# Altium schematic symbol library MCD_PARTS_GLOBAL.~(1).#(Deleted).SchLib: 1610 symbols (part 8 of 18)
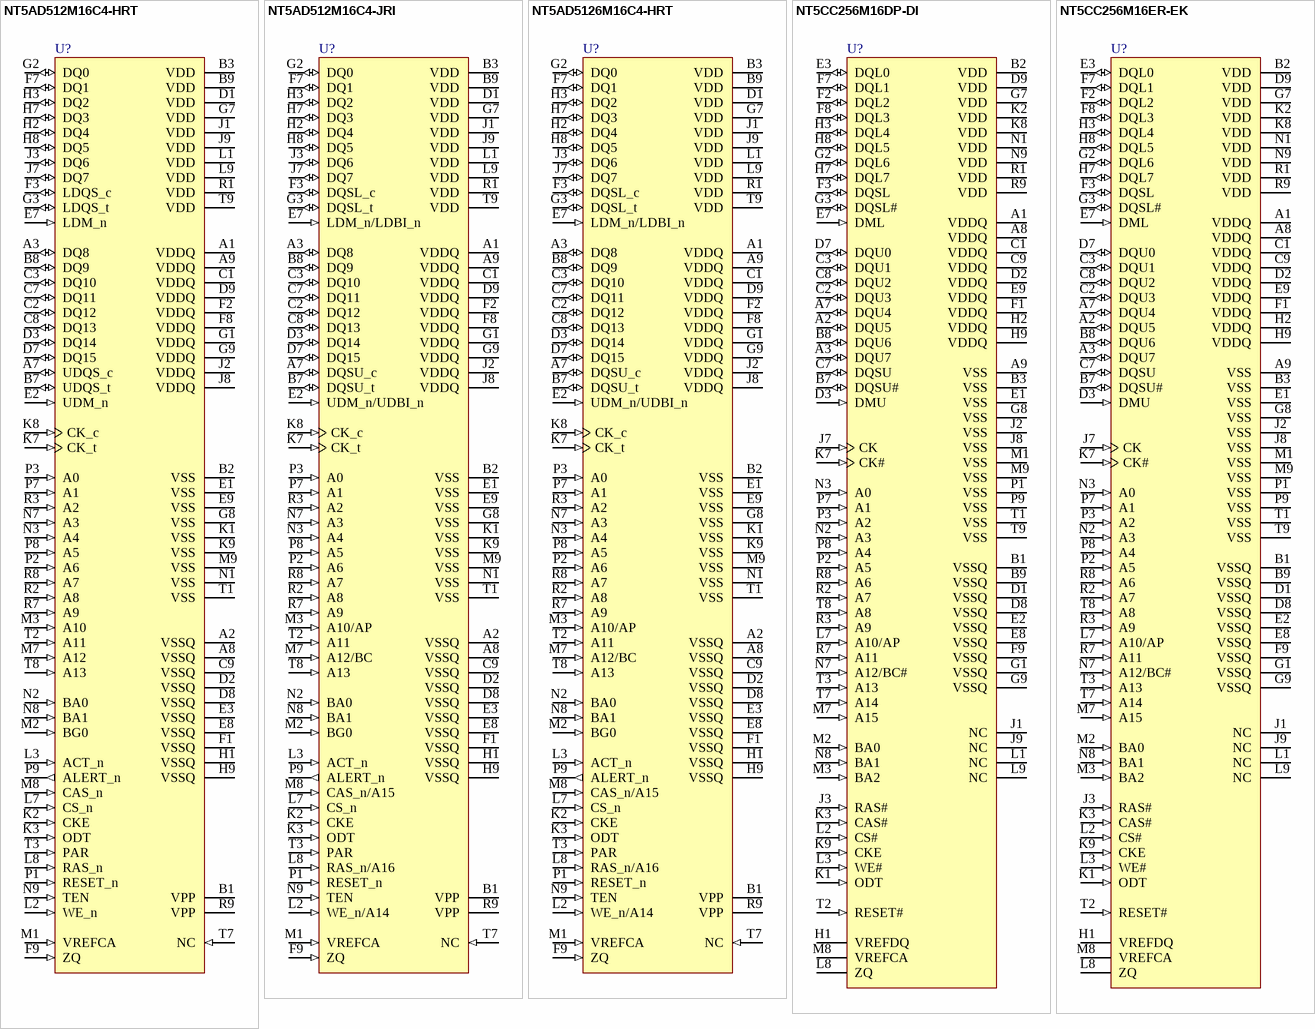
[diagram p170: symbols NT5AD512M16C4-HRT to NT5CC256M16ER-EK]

## NT5CC256M16DP-DI
designator U?
pins: A1 VDDQ (power) "DQ Power Supply: 1.5 V +/- 0.075 V for standard voltage or 1.35V +0.1V, -0.067V for low voltage", A2 DQU5 (io) "Data Input/ Output: Bi-directional data bus.", A3 DQU7 (io) "Data Input/ Output: Bi-directional data bus.", A7 DQU4 (io) "Data Input/ Output: Bi-directional data bus.", A8 VDDQ (power) "DQ Power Supply: 1.5 V +/- 0.075 V for standard voltage or 1.35V +0.1V, -0.067V for low voltage", A9 VSS (power) "Ground", B1 VSSQ (power) "DQ Ground", B2 VDD (power) "Power Supply: 1.5 V +/- 0.075 V for standard voltage or 1.35V +0.1V, -0.067V for low voltage", B3 VSS (power) "Ground", B7 DQSU# (io) "Data Strobe: output with read data, input with write data. Edge-aligned with read data, centered in write data. For the x16, DQSL corresponds to the data on DQL0-DQL7; DQSU corresponds to the data on DQU0-DQU7. The data strobes DQS, DQSL, and DQSU are paired with differential signals DQS#, DQSL#, and DQSU#, respectively, to provide differential pair signaling to the system during reads and writes. DDR3 SDRAM supports differential data strobe only and does not support single-ended.", B8 DQU6 (io) "Data Input/ Output: Bi-directional data bus.", B9 VSSQ (power) "DQ Ground", C1 VDDQ (power) "DQ Power Supply: 1.5 V +/- 0.075 V for standard voltage or 1.35V +0.1V, -0.067V for low voltage", C2 DQU3 (io) "Data Input/ Output: Bi-directional data bus.", C3 DQU1 (io) "Data Input/ Output: Bi-directional data bus.", C7 DQSU (io) "Data Strobe: output with read data, input with write data. Edge-aligned with read data, centered in write data. For the x16, DQSL corresponds to the data on DQL0-DQL7; DQSU corresponds to the data on DQU0-DQU7. The data strobes DQS, DQSL, and DQSU are paired with differential signals DQS#, DQSL#, and DQSU#, respectively, to provide differential pair signaling to the system during reads and writes. DDR3 SDRAM supports differential data strobe only and does not support single-ended.", C8 DQU2 (io) "Data Input/ Output: Bi-directional data bus.", C9 VDDQ (power) "DQ Power Supply: 1.5 V +/- 0.075 V for standard voltage or 1.35V +0.1V, -0.067V for low voltage", D1 VSSQ (power) "DQ Ground", D2 VDDQ (power) "DQ Power Supply: 1.5 V +/- 0.075 V for standard voltage or 1.35V +0.1V, -0.067V for low voltage", D3 DMU (in) "Input Data Mask: DM is an input mask signal for write data. Input data is masked when DM is sampled HIGH coincident with that input data during a Write access. DM is sampled on both edges of DQS. For x8 device, the function of DM or TDQS/TDQS# is enabled by Mode Register A11 setting in MR1.", D7 DQU0 (io) "Data Input/ Output: Bi-directional data bus.", D8 VSSQ (power) "DQ Ground", D9 VDD (power) "Power Supply: 1.5 V +/- 0.075 V for standard voltage or 1.35V +0.1V, -0.067V for low voltage", E1 VSS (power) "Ground", E2 VSSQ (power) "DQ Ground", E3 DQL0 (io) "Data Input/ Output: Bi-directional data bus.", E7 DML (in) "Input Data Mask: DM is an input mask signal for write data. Input data is masked when DM is sampled HIGH coincident with that input data during a Write access. DM is sampled on both edges of DQS. For x8 device, the function of DM or TDQS/TDQS# is enabled by Mode Register A11 setting in MR1.", E8 VSSQ (power) "DQ Ground", E9 VDDQ (power) "DQ Power Supply: 1.5 V +/- 0.075 V for standard voltage or 1.35V +0.1V, -0.067V for low voltage", F1 VDDQ (power) "DQ Power Supply: 1.5 V +/- 0.075 V for standard voltage or 1.35V +0.1V, -0.067V for low voltage", F2 DQL2 (io) "Data Input/ Output: Bi-directional data bus.", F3 DQSL (io) "Data Strobe: output with read data, input with write data. Edge-aligned with read data, centered in write data. For the x16, DQSL corresponds to the data on DQL0-DQL7; DQSU corresponds to the data on DQU0-DQU7. The data strobes DQS, DQSL, and DQSU are paired with differential signals DQS#, DQSL#, and DQSU#, respectively, to provide differential pair signaling to the system during reads and writes. DDR3 SDRAM supports differential data strobe only and does not support single-ended.", F7 DQL1 (io) "Data Input/ Output: Bi-directional data bus.", F8 DQL3 (io) "Data Input/ Output: Bi-directional data bus.", F9 VSSQ (power) "DQ Ground", G1 VSSQ (power) "DQ Ground", G2 DQL6 (io) "Data Input/ Output: Bi-directional data bus.", G3 DQSL# (io) "Data Strobe: output with read data, input with write data. Edge-aligned with read data, centered in write data. For the x16, DQSL corresponds to the data on DQL0-DQL7; DQSU corresponds to the data on DQU0-DQU7. The data strobes DQS, DQSL, and DQSU are paired with differential signals DQS#, DQSL#, and DQSU#, respectively, to provide differential pair signaling to the system during reads and writes. DDR3 SDRAM supports differential data strobe only and does not support single-ended.", G7 VDD (power) "Power Supply: 1.5 V +/- 0.075 V for standard voltage or 1.35V +0.1V, -0.067V for low voltage", G8 VSS (power) "Ground", G9 VSSQ (power) "DQ Ground", H1 VREFDQ "Reference voltage for DQ", H2 VDDQ (power) "DQ Power Supply: 1.5 V +/- 0.075 V for standard voltage or 1.35V +0.1V, -0.067V for low voltage", H3 DQL4 (io) "Data Input/ Output: Bi-directional data bus.", H7 DQL7 (io) "Data Input/ Output: Bi-directional data bus.", H8 DQL5 (io) "Data Input/ Output: Bi-directional data bus.", H9 VDDQ (power) "DQ Power Supply: 1.5 V +/- 0.075 V for standard voltage or 1.35V +0.1V, -0.067V for low voltage", J1 NC "No Connect: No internal electrical connection is present.", J2 VSS (power) "Ground", J3 RAS# (in) "Command Inputs: RAS#, CAS# and WE# (along with CS#) define the command being entered.", J7 CK (in) "Clock: CK and CK# are differential clock inputs. All address and control input signals are sampled on the crossing of the positive edge of CK and negative edge of CK#.", J8 VSS (power) "Ground", J9 NC "No Connect: No internal electrical connection is present.", K1 ODT (in) "On Die Termination: ODT (registered HIGH) enables termination resistance internal to the DDR3 SDRAM. When enabled, ODT is only applied to each DQ, DQSU, DQSU#, DQSL, DQSL#, DMU, and DML signal. The ODT pin will be ignored if MR1 and MR2 are programmed to disable RTT.", K2 VDD (power) "Power Supply: 1.5 V +/- 0.075 V for standard voltage or 1.35V +0.1V, -0.067V for low voltage", K3 CAS# (in) "Command Inputs: RAS#, CAS# and WE# (along with CS#) define the command being entered.", K7 CK# (in) "Clock: CK and CK# are differential clock inputs. All address and control input signals are sampled on the crossing of the positive edge of CK and negative edge of CK#.", K8 VDD (power) "Power Supply: 1.5 V +/- 0.075 V for standard voltage or 1.35V +0.1V, -0.067V for low voltage", K9 CKE (in) "Clock Enable: CKE HIGH activates, and CKE Low deactivates, internal clock signals and device input buffers and output drivers. Taking CKE Low provides Precharge Power-Down and Self-Refresh operation (all banks idle), or Active Power-Down (row Active in any bank). CKE is asynchronous for Self-Refresh exit. After VREFCA and VREFDQ have become stable during the power on and initialization sequence, they must be maintained during all operations (including Self-Refresh). CKE must be maintained high throughout read and write accesses. Input buffers, excluding CK, CK#, ODT and CKE, are disabled during power-down. Input buffers, excluding CKE, are disabled during Self-Refresh.", L1 NC "No Connect: No internal electrical connection is present.", L2 CS# (in) "Chip Select: All commands are masked when CS# is registered HIGH. CS# provides for external Rank selection on systems with multiple Ranks. CS# is considered part of the command code.", L3 WE# (in) "Command Inputs: RAS#, CAS# and WE# (along with CS#) define the command being entered.", L7 A10/AP (in) "Auto-precharge: A10 is sampled during Read/Write commands to determine whether Autoprecharge should be performed to the accessed bank after the Read/Write operation. (HIGH: Autoprecharge; LOW: no Autoprecharge). A10 is sampled during a Precharge command to determine whether the Precharge applies to one bank (A10 LOW) or all banks (A10 HIGH). If only one bank is to be precharged, the bank is selected by bank addresses.", L8 ZQ "Reference Pin for ZQ", L9 NC "No Connect: No internal electrical connection is present.", M1 VSS (power) "Ground", M2 BA0 (in) "Bank Address Inputs: BA0 - BA2 define to which bank an Active, Read, Write, or Precharge command is being applied. Bank address also determines which mode register is to be accessed during a MRS cycle.", M3 BA2 (in) "Bank Address Inputs: BA0 - BA2 define to which bank an Active, Read, Write, or Precharge command is being applied. Bank address also determines which mode register is to be accessed during a MRS cycle.", M7 A15 (in) "Burst Chop: A12 / BC# is sampled during Read and Write commands to determine if burst chop (on-the-fly) will be performed. (HIGH, no burst chop; LOW: burst chopped). See command truth table for details.", M8 VREFCA "Reference voltage for CA", M9 VSS (power) "Ground", N1 VDD (power) "Power Supply: 1.5 V +/- 0.075 V for standard voltage or 1.35V +0.1V, -0.067V for low voltage", N2 A3 (in) "Address Inputs: Provide the row address for Active commands and the column address for Read/ Write commands to select one location out of the memory array in the respective bank. (A10/AP and A12/BC# have additional functions; see below). The address inputs also provide the op-code during Mode Register Set commands.", N3 A0 (in) "Address Inputs: Provide the row address for Active commands and the column address for Read/ Write commands to select one location out of the memory array in the respective bank. (A10/AP and A12/BC# have additional functions; see below). The address inputs also provide the op-code during Mode Register Set commands.", N7 A12/BC# (in) "Burst Chop: A12 / BC# is sampled during Read and Write commands to determine if burst chop (on-the-fly) will be performed. (HIGH, no burst chop; LOW: burst chopped). See command truth table for details.", N8 BA1 (in) "Bank Address Inputs: BA0 - BA2 define to which bank an Active, Read, Write, or Precharge command is being applied. Bank address also determines which mode register is to be accessed during a MRS cycle.", N9 VDD (power) "Power Supply: 1.5 V +/- 0.075 V for standard voltage or 1.35V +0.1V, -0.067V for low voltage", P1 VSS (power) "Ground", P2 A5 (in) "Address Inputs: Provide the row address for Active commands and the column address for Read/ Write commands to select one location out of the memory array in the respective bank. (A10/AP and A12/BC# have additional functions; see below). The address inputs also provide the op-code during Mode Register Set commands.", P3 A2 (in) "Address Inputs: Provide the row address for Active commands and the column address for Read/ Write commands to select one location out of the memory array in the respective bank. (A10/AP and A12/BC# have additional functions; see below). The address inputs also provide the op-code during Mode Register Set commands.", P7 A1 (in) "Address Inputs: Provide the row address for Active commands and the column address for Read/ Write commands to select one location out of the memory array in the respective bank. (A10/AP and A12/BC# have additional functions; see below). The address inputs also provide the op-code during Mode Register Set commands.", P8 A4 (in) "Address Inputs: Provide the row address for Active commands and the column address for Read/ Write commands to select one location out of the memory array in the respective bank. (A10/AP and A12/BC# have additional functions; see below). The address inputs also provide the op-code during Mode Register Set commands.", P9 VSS (power) "Ground", R1 VDD (power) "Power Supply: 1.5 V +/- 0.075 V for standard voltage or 1.35V +0.1V, -0.067V for low voltage", R2 A7 (in) "Address Inputs: Provide the row address for Active commands and the column address for Read/ Write commands to select one location out of the memory array in the respective bank. (A10/AP and A12/BC# have additional functions; see below). The address inputs also provide the op-code during Mode Register Set commands.", R3 A9 (in) "Address Inputs: Provide the row address for Active commands and the column address for Read/ Write commands to select one location out of the memory array in the respective bank. (A10/AP and A12/BC# have additional functions; see below). The address inputs also provide the op-code during Mode Register Set commands.", R7 A11 (in) "Address Inputs: Provide the row address for Active commands and the column address for Read/ Write commands to select one location out of the memory array in the respective bank. (A10/AP and A12/BC# have additional functions; see below). The address inputs also provide the op-code during Mode Register Set commands.", R8 A6 (in) "Address Inputs: Provide the row address for Active commands and the column address for Read/ Write commands to select one location out of the memory array in the respective bank. (A10/AP and A12/BC# have additional functions; see below). The address inputs also provide the op-code during Mode Register Set commands.", R9 VDD (power) "Power Supply: 1.5 V +/- 0.075 V for standard voltage or 1.35V +0.1V, -0.067V for low voltage", T1 VSS (power) "Ground", T2 RESET# (in) "Active Low Asynchronous Reset: Reset is active when RESET# is LOW, and inactive when RESET# is HIGH. RESET# must be HIGH during normal operation. RESET# is a CMOS rail- to-rail signal with DC high and low at 80% and 20% of VDD, i.e., 1.20V for DC high and 0.30V for DC low.", T3 A13 (in) "Burst Chop: A12 / BC# is sampled during Read and Write commands to determine if burst chop (on-the-fly) will be performed. (HIGH, no burst chop; LOW: burst chopped). See command truth table for details.", T7 A14 (in) "Burst Chop: A12 / BC# is sampled during Read and Write commands to determine if burst chop (on-the-fly) will be performed. (HIGH, no burst chop; LOW: burst chopped). See command truth table for details.", T8 A8 (in) "Address Inputs: Provide the row address for Active commands and the column address for Read/ Write commands to select one location out of the memory array in the respective bank. (A10/AP and A12/BC# have additional functions; see below). The address inputs also provide the op-code during Mode Register Set commands.", T9 VSS (power) "Ground"

## NT5CC256M16ER-EK
designator U?
pins: A1 VDDQ (power) "DQ Power Supply: 1.5 V +/- 0.075 V for standard voltage or 1.35V +0.1V, -0.067V for low voltage", A2 DQU5 (io) "Data Input/ Output: Bi-directional data bus.", A3 DQU7 (io) "Data Input/ Output: Bi-directional data bus.", A7 DQU4 (io) "Data Input/ Output: Bi-directional data bus.", A8 VDDQ (power) "DQ Power Supply: 1.5 V +/- 0.075 V for standard voltage or 1.35V +0.1V, -0.067V for low voltage", A9 VSS (power) "Ground", B1 VSSQ (power) "DQ Ground", B2 VDD (power) "Power Supply: 1.5 V +/- 0.075 V for standard voltage or 1.35V +0.1V, -0.067V for low voltage", B3 VSS (power) "Ground", B7 DQSU# (io) "Data Strobe: output with read data, input with write data. Edge-aligned with read data, centered in write data. For the x16, DQSL corresponds to the data on DQL0-DQL7; DQSU corresponds to the data on DQU0-DQU7. The data strobes DQS, DQSL, and DQSU are paired with differential signals DQS#, DQSL#, and DQSU#, respectively, to provide differential pair signaling to the system during reads and writes. DDR3 SDRAM supports differential data strobe only and does not support single-ended.", B8 DQU6 (io) "Data Input/ Output: Bi-directional data bus.", B9 VSSQ (power) "DQ Ground", C1 VDDQ (power) "DQ Power Supply: 1.5 V +/- 0.075 V for standard voltage or 1.35V +0.1V, -0.067V for low voltage", C2 DQU3 (io) "Data Input/ Output: Bi-directional data bus.", C3 DQU1 (io) "Data Input/ Output: Bi-directional data bus.", C7 DQSU (io) "Data Strobe: output with read data, input with write data. Edge-aligned with read data, centered in write data. For the x16, DQSL corresponds to the data on DQL0-DQL7; DQSU corresponds to the data on DQU0-DQU7. The data strobes DQS, DQSL, and DQSU are paired with differential signals DQS#, DQSL#, and DQSU#, respectively, to provide differential pair signaling to the system during reads and writes. DDR3 SDRAM supports differential data strobe only and does not support single-ended.", C8 DQU2 (io) "Data Input/ Output: Bi-directional data bus.", C9 VDDQ (power) "DQ Power Supply: 1.5 V +/- 0.075 V for standard voltage or 1.35V +0.1V, -0.067V for low voltage", D1 VSSQ (power) "DQ Ground", D2 VDDQ (power) "DQ Power Supply: 1.5 V +/- 0.075 V for standard voltage or 1.35V +0.1V, -0.067V for low voltage", D3 DMU (in) "Input Data Mask: DM is an input mask signal for write data. Input data is masked when DM is sampled HIGH coincident with that input data during a Write access. DM is sampled on both edges of DQS. For x8 device, the function of DM or TDQS/TDQS# is enabled by Mode Register A11 setting in MR1.", D7 DQU0 (io) "Data Input/ Output: Bi-directional data bus.", D8 VSSQ (power) "DQ Ground", D9 VDD (power) "Power Supply: 1.5 V +/- 0.075 V for standard voltage or 1.35V +0.1V, -0.067V for low voltage", E1 VSS (power) "Ground", E2 VSSQ (power) "DQ Ground", E3 DQL0 (io) "Data Input/ Output: Bi-directional data bus.", E7 DML (in) "Input Data Mask: DM is an input mask signal for write data. Input data is masked when DM is sampled HIGH coincident with that input data during a Write access. DM is sampled on both edges of DQS. For x8 device, the function of DM or TDQS/TDQS# is enabled by Mode Register A11 setting in MR1.", E8 VSSQ (power) "DQ Ground", E9 VDDQ (power) "DQ Power Supply: 1.5 V +/- 0.075 V for standard voltage or 1.35V +0.1V, -0.067V for low voltage", F1 VDDQ (power) "DQ Power Supply: 1.5 V +/- 0.075 V for standard voltage or 1.35V +0.1V, -0.067V for low voltage", F2 DQL2 (io) "Data Input/ Output: Bi-directional data bus.", F3 DQSL (io) "Data Strobe: output with read data, input with write data. Edge-aligned with read data, centered in write data. For the x16, DQSL corresponds to the data on DQL0-DQL7; DQSU corresponds to the data on DQU0-DQU7. The data strobes DQS, DQSL, and DQSU are paired with differential signals DQS#, DQSL#, and DQSU#, respectively, to provide differential pair signaling to the system during reads and writes. DDR3 SDRAM supports differential data strobe only and does not support single-ended.", F7 DQL1 (io) "Data Input/ Output: Bi-directional data bus.", F8 DQL3 (io) "Data Input/ Output: Bi-directional data bus.", F9 VSSQ (power) "DQ Ground", G1 VSSQ (power) "DQ Ground", G2 DQL6 (io) "Data Input/ Output: Bi-directional data bus.", G3 DQSL# (io) "Data Strobe: output with read data, input with write data. Edge-aligned with read data, centered in write data. For the x16, DQSL corresponds to the data on DQL0-DQL7; DQSU corresponds to the data on DQU0-DQU7. The data strobes DQS, DQSL, and DQSU are paired with differential signals DQS#, DQSL#, and DQSU#, respectively, to provide differential pair signaling to the system during reads and writes. DDR3 SDRAM supports differential data strobe only and does not support single-ended.", G7 VDD (power) "Power Supply: 1.5 V +/- 0.075 V for standard voltage or 1.35V +0.1V, -0.067V for low voltage", G8 VSS (power) "Ground", G9 VSSQ (power) "DQ Ground", H1 VREFDQ "Reference voltage for DQ", H2 VDDQ (power) "DQ Power Supply: 1.5 V +/- 0.075 V for standard voltage or 1.35V +0.1V, -0.067V for low voltage", H3 DQL4 (io) "Data Input/ Output: Bi-directional data bus.", H7 DQL7 (io) "Data Input/ Output: Bi-directional data bus.", H8 DQL5 (io) "Data Input/ Output: Bi-directional data bus.", H9 VDDQ (power) "DQ Power Supply: 1.5 V +/- 0.075 V for standard voltage or 1.35V +0.1V, -0.067V for low voltage", J1 NC "No Connect: No internal electrical connection is present.", J2 VSS (power) "Ground", J3 RAS# (in) "Command Inputs: RAS#, CAS# and WE# (along with CS#) define the command being entered.", J7 CK (in) "Clock: CK and CK# are differential clock inputs. All address and control input signals are sampled on the crossing of the positive edge of CK and negative edge of CK#.", J8 VSS (power) "Ground", J9 NC "No Connect: No internal electrical connection is present.", K1 ODT (in) "On Die Termination: ODT (registered HIGH) enables termination resistance internal to the DDR3 SDRAM. When enabled, ODT is only applied to each DQ, DQSU, DQSU#, DQSL, DQSL#, DMU, and DML signal. The ODT pin will be ignored if MR1 and MR2 are programmed to disable RTT.", K2 VDD (power) "Power Supply: 1.5 V +/- 0.075 V for standard voltage or 1.35V +0.1V, -0.067V for low voltage", K3 CAS# (in) "Command Inputs: RAS#, CAS# and WE# (along with CS#) define the command being entered.", K7 CK# (in) "Clock: CK and CK# are differential clock inputs. All address and control input signals are sampled on the crossing of the positive edge of CK and negative edge of CK#.", K8 VDD (power) "Power Supply: 1.5 V +/- 0.075 V for standard voltage or 1.35V +0.1V, -0.067V for low voltage", K9 CKE (in) "Clock Enable: CKE HIGH activates, and CKE Low deactivates, internal clock signals and device input buffers and output drivers. Taking CKE Low provides Precharge Power-Down and Self-Refresh operation (all banks idle), or Active Power-Down (row Active in any bank). CKE is asynchronous for Self-Refresh exit. After VREFCA and VREFDQ have become stable during the power on and initialization sequence, they must be maintained during all operations (including Self-Refresh). CKE must be maintained high throughout read and write accesses. Input buffers, excluding CK, CK#, ODT and CKE, are disabled during power-down. Input buffers, excluding CKE, are disabled during Self-Refresh.", L1 NC "No Connect: No internal electrical connection is present.", L2 CS# (in) "Chip Select: All commands are masked when CS# is registered HIGH. CS# provides for external Rank selection on systems with multiple Ranks. CS# is considered part of the command code.", L3 WE# (in) "Command Inputs: RAS#, CAS# and WE# (along with CS#) define the command being entered.", L7 A10/AP (in) "Auto-precharge: A10 is sampled during Read/Write commands to determine whether Autoprecharge should be performed to the accessed bank after the Read/Write operation. (HIGH: Autoprecharge; LOW: no Autoprecharge). A10 is sampled during a Precharge command to determine whether the Precharge applies to one bank (A10 LOW) or all banks (A10 HIGH). If only one bank is to be precharged, the bank is selected by bank addresses.", L8 ZQ "Reference Pin for ZQ", L9 NC "No Connect: No internal electrical connection is present.", M1 VSS (power) "Ground", M2 BA0 (in) "Bank Address Inputs: BA0 - BA2 define to which bank an Active, Read, Write, or Precharge command is being applied. Bank address also determines which mode register is to be accessed during a MRS cycle.", M3 BA2 (in) "Bank Address Inputs: BA0 - BA2 define to which bank an Active, Read, Write, or Precharge command is being applied. Bank address also determines which mode register is to be accessed during a MRS cycle.", M7 A15 (in) "Burst Chop: A12 / BC# is sampled during Read and Write commands to determine if burst chop (on-the-fly) will be performed. (HIGH, no burst chop; LOW: burst chopped). See command truth table for details.", M8 VREFCA "Reference voltage for CA", M9 VSS (power) "Ground", N1 VDD (power) "Power Supply: 1.5 V +/- 0.075 V for standard voltage or 1.35V +0.1V, -0.067V for low voltage", N2 A3 (in) "Address Inputs: Provide the row address for Active commands and the column address for Read/ Write commands to select one location out of the memory array in the respective bank. (A10/AP and A12/BC# have additional functions; see below). The address inputs also provide the op-code during Mode Register Set commands.", N3 A0 (in) "Address Inputs: Provide the row address for Active commands and the column address for Read/ Write commands to select one location out of the memory array in the respective bank. (A10/AP and A12/BC# have additional functions; see below). The address inputs also provide the op-code during Mode Register Set commands.", N7 A12/BC# (in) "Burst Chop: A12 / BC# is sampled during Read and Write commands to determine if burst chop (on-the-fly) will be performed. (HIGH, no burst chop; LOW: burst chopped). See command truth table for details.", N8 BA1 (in) "Bank Address Inputs: BA0 - BA2 define to which bank an Active, Read, Write, or Precharge command is being applied. Bank address also determines which mode register is to be accessed during a MRS cycle.", N9 VDD (power) "Power Supply: 1.5 V +/- 0.075 V for standard voltage or 1.35V +0.1V, -0.067V for low voltage", P1 VSS (power) "Ground", P2 A5 (in) "Address Inputs: Provide the row address for Active commands and the column address for Read/ Write commands to select one location out of the memory array in the respective bank. (A10/AP and A12/BC# have additional functions; see below). The address inputs also provide the op-code during Mode Register Set commands.", P3 A2 (in) "Address Inputs: Provide the row address for Active commands and the column address for Read/ Write commands to select one location out of the memory array in the respective bank. (A10/AP and A12/BC# have additional functions; see below). The address inputs also provide the op-code during Mode Register Set commands.", P7 A1 (in) "Address Inputs: Provide the row address for Active commands and the column address for Read/ Write commands to select one location out of the memory array in the respective bank. (A10/AP and A12/BC# have additional functions; see below). The address inputs also provide the op-code during Mode Register Set commands.", P8 A4 (in) "Address Inputs: Provide the row address for Active commands and the column address for Read/ Write commands to select one location out of the memory array in the respective bank. (A10/AP and A12/BC# have additional functions; see below). The address inputs also provide the op-code during Mode Register Set commands.", P9 VSS (power) "Ground", R1 VDD (power) "Power Supply: 1.5 V +/- 0.075 V for standard voltage or 1.35V +0.1V, -0.067V for low voltage", R2 A7 (in) "Address Inputs: Provide the row address for Active commands and the column address for Read/ Write commands to select one location out of the memory array in the respective bank. (A10/AP and A12/BC# have additional functions; see below). The address inputs also provide the op-code during Mode Register Set commands.", R3 A9 (in) "Address Inputs: Provide the row address for Active commands and the column address for Read/ Write commands to select one location out of the memory array in the respective bank. (A10/AP and A12/BC# have additional functions; see below). The address inputs also provide the op-code during Mode Register Set commands.", R7 A11 (in) "Address Inputs: Provide the row address for Active commands and the column address for Read/ Write commands to select one location out of the memory array in the respective bank. (A10/AP and A12/BC# have additional functions; see below). The address inputs also provide the op-code during Mode Register Set commands.", R8 A6 (in) "Address Inputs: Provide the row address for Active commands and the column address for Read/ Write commands to select one location out of the memory array in the respective bank. (A10/AP and A12/BC# have additional functions; see below). The address inputs also provide the op-code during Mode Register Set commands.", R9 VDD (power) "Power Supply: 1.5 V +/- 0.075 V for standard voltage or 1.35V +0.1V, -0.067V for low voltage", T1 VSS (power) "Ground", T2 RESET# (in) "Active Low Asynchronous Reset: Reset is active when RESET# is LOW, and inactive when RESET# is HIGH. RESET# must be HIGH during normal operation. RESET# is a CMOS rail- to-rail signal with DC high and low at 80% and 20% of VDD, i.e., 1.20V for DC high and 0.30V for DC low.", T3 A13 (in) "Burst Chop: A12 / BC# is sampled during Read and Write commands to determine if burst chop (on-the-fly) will be performed. (HIGH, no burst chop; LOW: burst chopped). See command truth table for details.", T7 A14 (in) "Burst Chop: A12 / BC# is sampled during Read and Write commands to determine if burst chop (on-the-fly) will be performed. (HIGH, no burst chop; LOW: burst chopped). See command truth table for details.", T8 A8 (in) "Address Inputs: Provide the row address for Active commands and the column address for Read/ Write commands to select one location out of the memory array in the respective bank. (A10/AP and A12/BC# have additional functions; see below). The address inputs also provide the op-code during Mode Register Set commands.", T9 VSS (power) "Ground"
1 alternate drawing of the same symbol

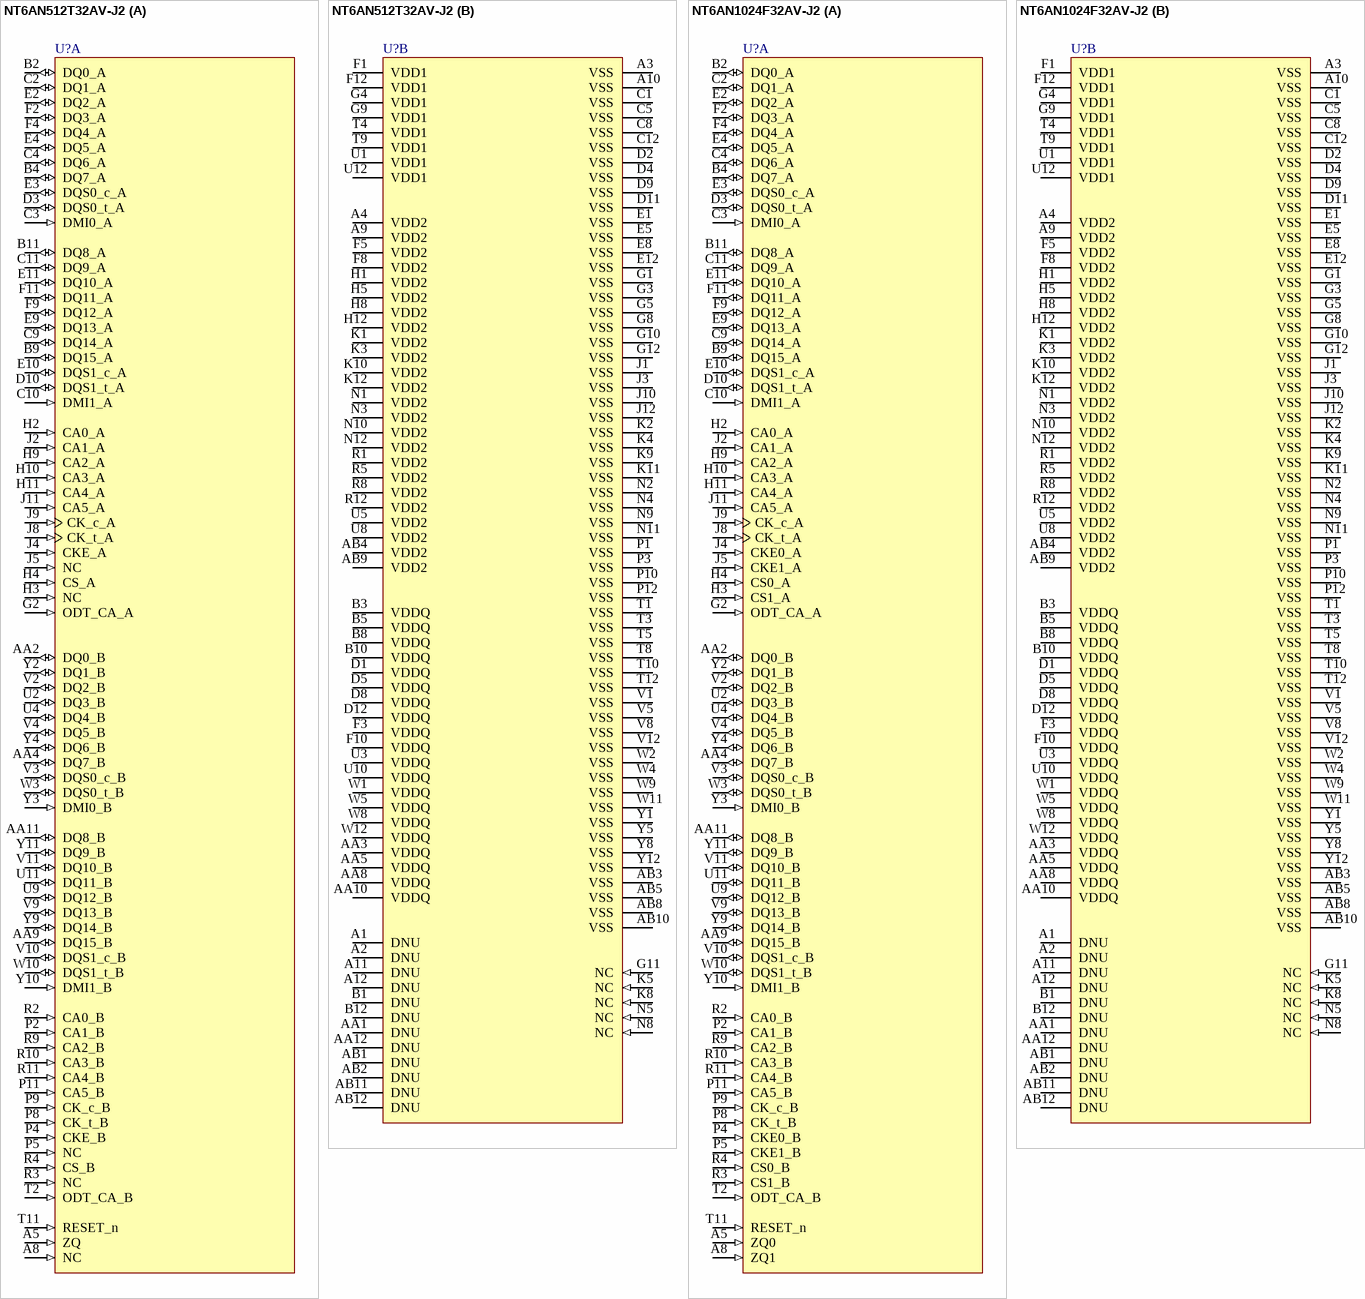
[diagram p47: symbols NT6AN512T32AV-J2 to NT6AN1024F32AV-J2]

## NT6AN512T32AV-J2
designator U?
part A pins: A5 ZQ (in) "External impedance (240 ohm): This signal is used to calibrate the device output impedance.", A8 NC (in), AA2 DQ0_B (io) "Data input/output: Bidirectional data bus.", AA4 DQ7_B (io) "Data input/output: Bidirectional data bus.", AA9 DQ15_B (io) "Data input/output: Bidirectional data bus.", AA11 DQ8_B (io) "Data input/output: Bidirectional data bus.", B2 DQ0_A (io) "Data input/output: Bidirectional data bus.", B4 DQ7_A (io) "Data input/output: Bidirectional data bus.", B9 DQ15_A (io) "Data input/output: Bidirectional data bus.", B11 DQ8_A (io) "Data input/output: Bidirectional data bus.", C2 DQ1_A (io) "Data input/output: Bidirectional data bus.", C3 DMI0_A (in) "Input data mask: DM is an input mask signal for write data. Although DM ballsare input-only, the DM loading is designed to match that of DQ and DQS balls.DM[3:0] is DM for each of the four data bytes, respectively.", C4 DQ6_A (io) "Data input/output: Bidirectional data bus.", C9 DQ14_A (io) "Data input/output: Bidirectional data bus.", C10 DMI1_A (in) "Input data mask: DM is an input mask signal for write data. Although DM ballsare input-only, the DM loading is designed to match that of DQ and DQS balls.DM[3:0] is DM for each of the four data bytes, respectively.", C11 DQ9_A (io) "Data input/output: Bidirectional data bus.", D3 DQS0_t_A (io) "Data strobe: The data strobe is bidirectional (used for read and write data) andcomplementary (DQS and DQS#). It is edge-aligned output with read data andcentered input with write data. DQS[3:0]/DQS[3:0]# is DQS for each of (See Datasheet)", D10 DQS1_t_A (io) "Data strobe: The data strobe is bidirectional (used for read and write data) andcomplementary (DQS and DQS#). It is edge-aligned output with read data andcentered input with write data. DQS[3:0]/DQS[3:0]# is DQS for each of (See Datasheet)", E2 DQ2_A (io) "Data input/output: Bidirectional data bus.", E3 DQS0_c_A (io) "Data strobe: The data strobe is bidirectional (used for read and write data) andcomplementary (DQS and DQS#). It is edge-aligned output with read data andcentered input with write data. DQS[3:0]/DQS[3:0]# is DQS for each of (See Datasheet)", E4 DQ5_A (io) "Data input/output: Bidirectional data bus.", E9 DQ13_A (io) "Data input/output: Bidirectional data bus.", E10 DQS1_c_A (io) "Data strobe: The data strobe is bidirectional (used for read and write data) andcomplementary (DQS and DQS#). It is edge-aligned output with read data andcentered input with write data. DQS[3:0]/DQS[3:0]# is DQS for each of (See Datasheet)", E11 DQ10_A (io) "Data input/output: Bidirectional data bus.", F2 DQ3_A (io) "Data input/output: Bidirectional data bus.", F4 DQ4_A (io) "Data input/output: Bidirectional data bus.", F9 DQ12_A (io) "Data input/output: Bidirectional data bus.", F11 DQ11_A (io) "Data input/output: Bidirectional data bus.", G2 ODT_CA_A (in) "on die termination on CA", H2 CA0_A (in) "Command/address inputs: Provide the command and address inputs accordingto the command truth table.", H3 NC (in), H4 CS_A (in) "Chip select: CS# is considered part of the command code and is sampled at therising edge of CK.", H9 CA2_A (in) "Command/address inputs: Provide the command and address inputs accordingto the command truth table.", H10 CA3_A (in) "Command/address inputs: Provide the command and address inputs accordingto the command truth table.", H11 CA4_A (in) "Command/address inputs: Provide the command and address inputs accordingto the command truth table.", J2 CA1_A (in) "Command/address inputs: Provide the command and address inputs accordingto the command truth table.", J4 CKE_A (in) "Clock enable: CKE HIGH activates and CKE LOW deactivates the internal clocksignals, input buffers, and output drivers. Power-saving modes are entered andexited via CKE transitions. CKE is considered part of the command code. (See Datasheet)", J5 NC (in), J8 CK_t_A (in) "Clock: CK and CK# are differential clock inputs. All CA inputs are sampled onboth rising and falling edges of CK. CS and CKE inputs are sampled at the risingedge of CK. AC timings are referenced to clock.", J9 CK_c_A (in) "Clock: CK and CK# are differential clock inputs. All CA inputs are sampled onboth rising and falling edges of CK. CS and CKE inputs are sampled at the risingedge of CK. AC timings are referenced to clock.", J11 CA5_A (in) "Command/address inputs: Provide the command and address inputs accordingto the command truth table.", P2 CA1_B (in) "Command/address inputs: Provide the command and address inputs accordingto the command truth table.", P4 CKE_B (in) "Clock enable: CKE HIGH activates and CKE LOW deactivates the internal clocksignals, input buffers, and output drivers. Power-saving modes are entered andexited via CKE transitions. CKE is considered part of the command code. (See Datasheet)", P5 NC (in), P8 CK_t_B (in) "Clock: CK and CK# are differential clock inputs. All CA inputs are sampled onboth rising and falling edges of CK. CS and CKE inputs are sampled at the risingedge of CK. AC timings are referenced to clock.", P9 CK_c_B (in) "Clock: CK and CK# are differential clock inputs. All CA inputs are sampled onboth rising and falling edges of CK. CS and CKE inputs are sampled at the risingedge of CK. AC timings are referenced to clock.", P11 CA5_B (in) "Command/address inputs: Provide the command and address inputs accordingto the command truth table.", R2 CA0_B (in) "Command/address inputs: Provide the command and address inputs accordingto the command truth table.", R3 NC (in), R4 CS_B (in) "Chip select: CS# is considered part of the command code and is sampled at therising edge of CK.", R9 CA2_B (in) "Command/address inputs: Provide the command and address inputs accordingto the command truth table.", R10 CA3_B (in) "Command/address inputs: Provide the command and address inputs accordingto the command truth table.", R11 CA4_B (in) "Command/address inputs: Provide the command and address inputs accordingto the command truth table.", T2 ODT_CA_B (in) "on die termination on CA", T11 RESET_n (in) "Reset active low", U2 DQ3_B (io) "Data input/output: Bidirectional data bus.", U4 DQ4_B (io) "Data input/output: Bidirectional data bus.", U9 DQ12_B (io) "Data input/output: Bidirectional data bus.", U11 DQ11_B (io) "Data input/output: Bidirectional data bus.", V2 DQ2_B (io) "Data input/output: Bidirectional data bus.", V3 DQS0_c_B (io) "Data strobe: The data strobe is bidirectional (used for read and write data) andcomplementary (DQS and DQS#). It is edge-aligned output with read data andcentered input with write data. DQS[3:0]/DQS[3:0]# is DQS for each of (See Datasheet)", V4 DQ5_B (io) "Data input/output: Bidirectional data bus.", V9 DQ13_B (io) "Data input/output: Bidirectional data bus.", V10 DQS1_c_B (io) "Data strobe: The data strobe is bidirectional (used for read and write data) andcomplementary (DQS and DQS#). It is edge-aligned output with read data andcentered input with write data. DQS[3:0]/DQS[3:0]# is DQS for each of (See Datasheet)", V11 DQ10_B (io) "Data input/output: Bidirectional data bus.", W3 DQS0_t_B (io) "Data strobe: The data strobe is bidirectional (used for read and write data) andcomplementary (DQS and DQS#). It is edge-aligned output with read data andcentered input with write data. DQS[3:0]/DQS[3:0]# is DQS for each of (See Datasheet)", W10 DQS1_t_B (io) "Data strobe: The data strobe is bidirectional (used for read and write data) andcomplementary (DQS and DQS#). It is edge-aligned output with read data andcentered input with write data. DQS[3:0]/DQS[3:0]# is DQS for each of (See Datasheet)", Y2 DQ1_B (io) "Data input/output: Bidirectional data bus.", Y3 DMI0_B (in) "Input data mask: DM is an input mask signal for write data. Although DM ballsare input-only, the DM loading is designed to match that of DQ and DQS balls.DM[3:0] is DM for each of the four data bytes, respectively.", Y4 DQ6_B (io) "Data input/output: Bidirectional data bus.", Y9 DQ14_B (io) "Data input/output: Bidirectional data bus.", Y10 DMI1_B (in) "Input data mask: DM is an input mask signal for write data. Although DM ballsare input-only, the DM loading is designed to match that of DQ and DQS balls.DM[3:0] is DM for each of the four data bytes, respectively.", Y11 DQ9_B (io) "Data input/output: Bidirectional data bus."
part B pins: A1 DNU "Do not use: Must be grounded or left floating.", A2 DNU "Do not use: Must be grounded or left floating.", A3 VSS (power) "Common ground.", A4 VDD2 (power) "Core power: Supply 2.", A9 VDD2 (power) "Core power: Supply 2.", A10 VSS (power) "Common ground.", A11 DNU "Do not use: Must be grounded or left floating.", A12 DNU "Do not use: Must be grounded or left floating.", AA1 DNU "Do not use: Must be grounded or left floating.", AA3 VDDQ (power) "DQ power supply: Isolated on the die for improved noise immunity.", AA5 VDDQ (power) "DQ power supply: Isolated on the die for improved noise immunity.", AA8 VDDQ (power) "DQ power supply: Isolated on the die for improved noise immunity.", AA10 VDDQ (power) "DQ power supply: Isolated on the die for improved noise immunity.", AA12 DNU "Do not use: Must be grounded or left floating.", AB1 DNU "Do not use: Must be grounded or left floating.", AB2 DNU "Do not use: Must be grounded or left floating.", AB3 VSS "Common ground.", AB4 VDD2 (power) "Core power: Supply 2.", AB5 VSS "Common ground.", AB8 VSS "Common ground.", AB9 VDD2 (power) "Core power: Supply 2.", AB10 VSS "Common ground.", AB11 DNU "Do not use: Must be grounded or left floating.", AB12 DNU "Do not use: Must be grounded or left floating.", B1 DNU "Do not use: Must be grounded or left floating.", B3 VDDQ (power) "DQ power supply: Isolated on the die for improved noise immunity.", B5 VDDQ (power) "DQ power supply: Isolated on the die for improved noise immunity.", B8 VDDQ (power) "DQ power supply: Isolated on the die for improved noise immunity.", B10 VDDQ (power) "DQ power supply: Isolated on the die for improved noise immunity.", B12 DNU "Do not use: Must be grounded or left floating.", C1 VSS (power) "Common ground.", C5 VSS (power) "Common ground.", C8 VSS (power) "Common ground.", C12 VSS (power) "Common ground.", D1 VDDQ (power) "DQ power supply: Isolated on the die for improved noise immunity.", D2 VSS (power) "Common ground.", D4 VSS (power) "Common ground.", D5 VDDQ (power) "DQ power supply: Isolated on the die for improved noise immunity.", D8 VDDQ (power) "DQ power supply: Isolated on the die for improved noise immunity.", D9 VSS (power) "Common ground.", D11 VSS (power) "Common ground.", D12 VDDQ (power) "DQ power supply: Isolated on the die for improved noise immunity.", E1 VSS (power) "Common ground.", E5 VSS (power) "Common ground.", E8 VSS (power) "Common ground.", E12 VSS (power) "Common ground.", F1 VDD1 (power) "Core power: Supply 1.", F3 VDDQ (power) "DQ power supply: Isolated on the die for improved noise immunity.", F5 VDD2 (power) "Core power: Supply 2.", F8 VDD2 (power) "Core power: Supply 2.", F10 VDDQ (power) "DQ power supply: Isolated on the die for improved noise immunity.", F12 VDD1 (power) "Core power: Supply 1.", G1 VSS (power) "Common ground.", G3 VSS (power) "Common ground.", G4 VDD1 (power) "Core power: Supply 1.", G5 VSS (power) "Common ground.", G8 VSS (power) "Common ground.", G9 VDD1 (power) "Core power: Supply 1.", G10 VSS (power) "Common ground.", G11 NC (in) "Not connected", G12 VSS (power) "Common ground.", H1 VDD2 (power) "Core power: Supply 2.", H5 VDD2 (power) "Core power: Supply 2.", H8 VDD2 (power) "Core power: Supply 2.", H12 VDD2 (power) "Core power: Supply 2.", J1 VSS (power) "Common ground.", J3 VSS (power) "Common ground.", J10 VSS (power) "Common ground.", J12 VSS (power) "Common ground.", K1 VDD2 (power) "Core power: Supply 2.", K2 VSS (power) "Common ground.", K3 VDD2 (power) "Core power: Supply 2.", K4 VSS (power) "Common ground.", K5 NC (in) "Not connected", K8 NC (in) "Not connected", K9 VSS (power) "Common ground.", K10 VDD2 (power) "Core power: Supply 2.", K11 VSS "Common ground.", K12 VDD2 (power) "Core power: Supply 2.", N1 VDD2 (power) "Core power: Supply 2.", N2 VSS "Common ground.", N3 VDD2 (power) "Core power: Supply 2.", N4 VSS "Common ground.", N5 NC (in) "Not connected", N8 NC (in) "Not connected", N9 VSS "Common ground.", N10 VDD2 (power) "Core power: Supply 2.", N11 VSS "Common ground.", N12 VDD2 (power) "Core power: Supply 2.", P1 VSS "Common ground.", P3 VSS (power) "Common ground.", P10 VSS (power) "Common ground.", P12 VSS "Common ground.", R1 VDD2 (power) "Core power: Supply 2.", R5 VDD2 (power) "Core power: Supply 2.", R8 VDD2 (power) "Core power: Supply 2.", R12 VDD2 (power) "Core power: Supply 2.", T1 VSS "Common ground.", T3 VSS "Common ground.", T4 VDD1 (power) "Core power: Supply 1.", T5 VSS "Common ground.", T8 VSS "Common ground.", T9 VDD1 (power) "Core power: Supply 1.", T10 VSS "Common ground.", T12 VSS "Common ground.", U1 VDD1 (power) "Core power: Supply 1.", U3 VDDQ (power) "DQ power supply: Isolated on the die for improved noise immunity.", U5 VDD2 (power) "Core power: Supply 2.", U8 VDD2 (power) "Core power: Supply 2.", U10 VDDQ (power) "DQ power supply: Isolated on the die for improved noise immunity.", U12 VDD1 (power) "Core power: Supply 1.", V1 VSS (power) "Common ground.", V5 VSS (power) "Common ground.", V8 VSS "Common ground.", V12 VSS "Common ground.", W1 VDDQ (power) "DQ power supply: Isolated on the die for improved noise immunity.", W2 VSS "Common ground.", W4 VSS "Common ground.", W5 VDDQ (power) "DQ power supply: Isolated on the die for improved noise immunity.", W8 VDDQ (power) "DQ power supply: Isolated on the die for improved noise immunity.", W9 VSS "Common ground.", W11 VSS "Common ground.", W12 VDDQ (power) "DQ power supply: Isolated on the die for improved noise immunity.", Y1 VSS "Common ground.", Y5 VSS "Common ground.", Y8 VSS "Common ground.", Y12 VSS "Common ground."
